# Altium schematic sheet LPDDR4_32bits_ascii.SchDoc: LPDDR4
size A3; Date: Not used; ApprovedBy: Not used; CheckedBy: Not used; Author: Not used; CompanyName: STMicroelectronics; DrawnBy: Not used; Engineer: Not used; Organization: Not used; Address1: Not used; Address2: Not used; Address3: Not used; Address4: Not used; DocumentNumber: 6; Revision: Not used; SheetNumber: 6; SheetTotal: 7
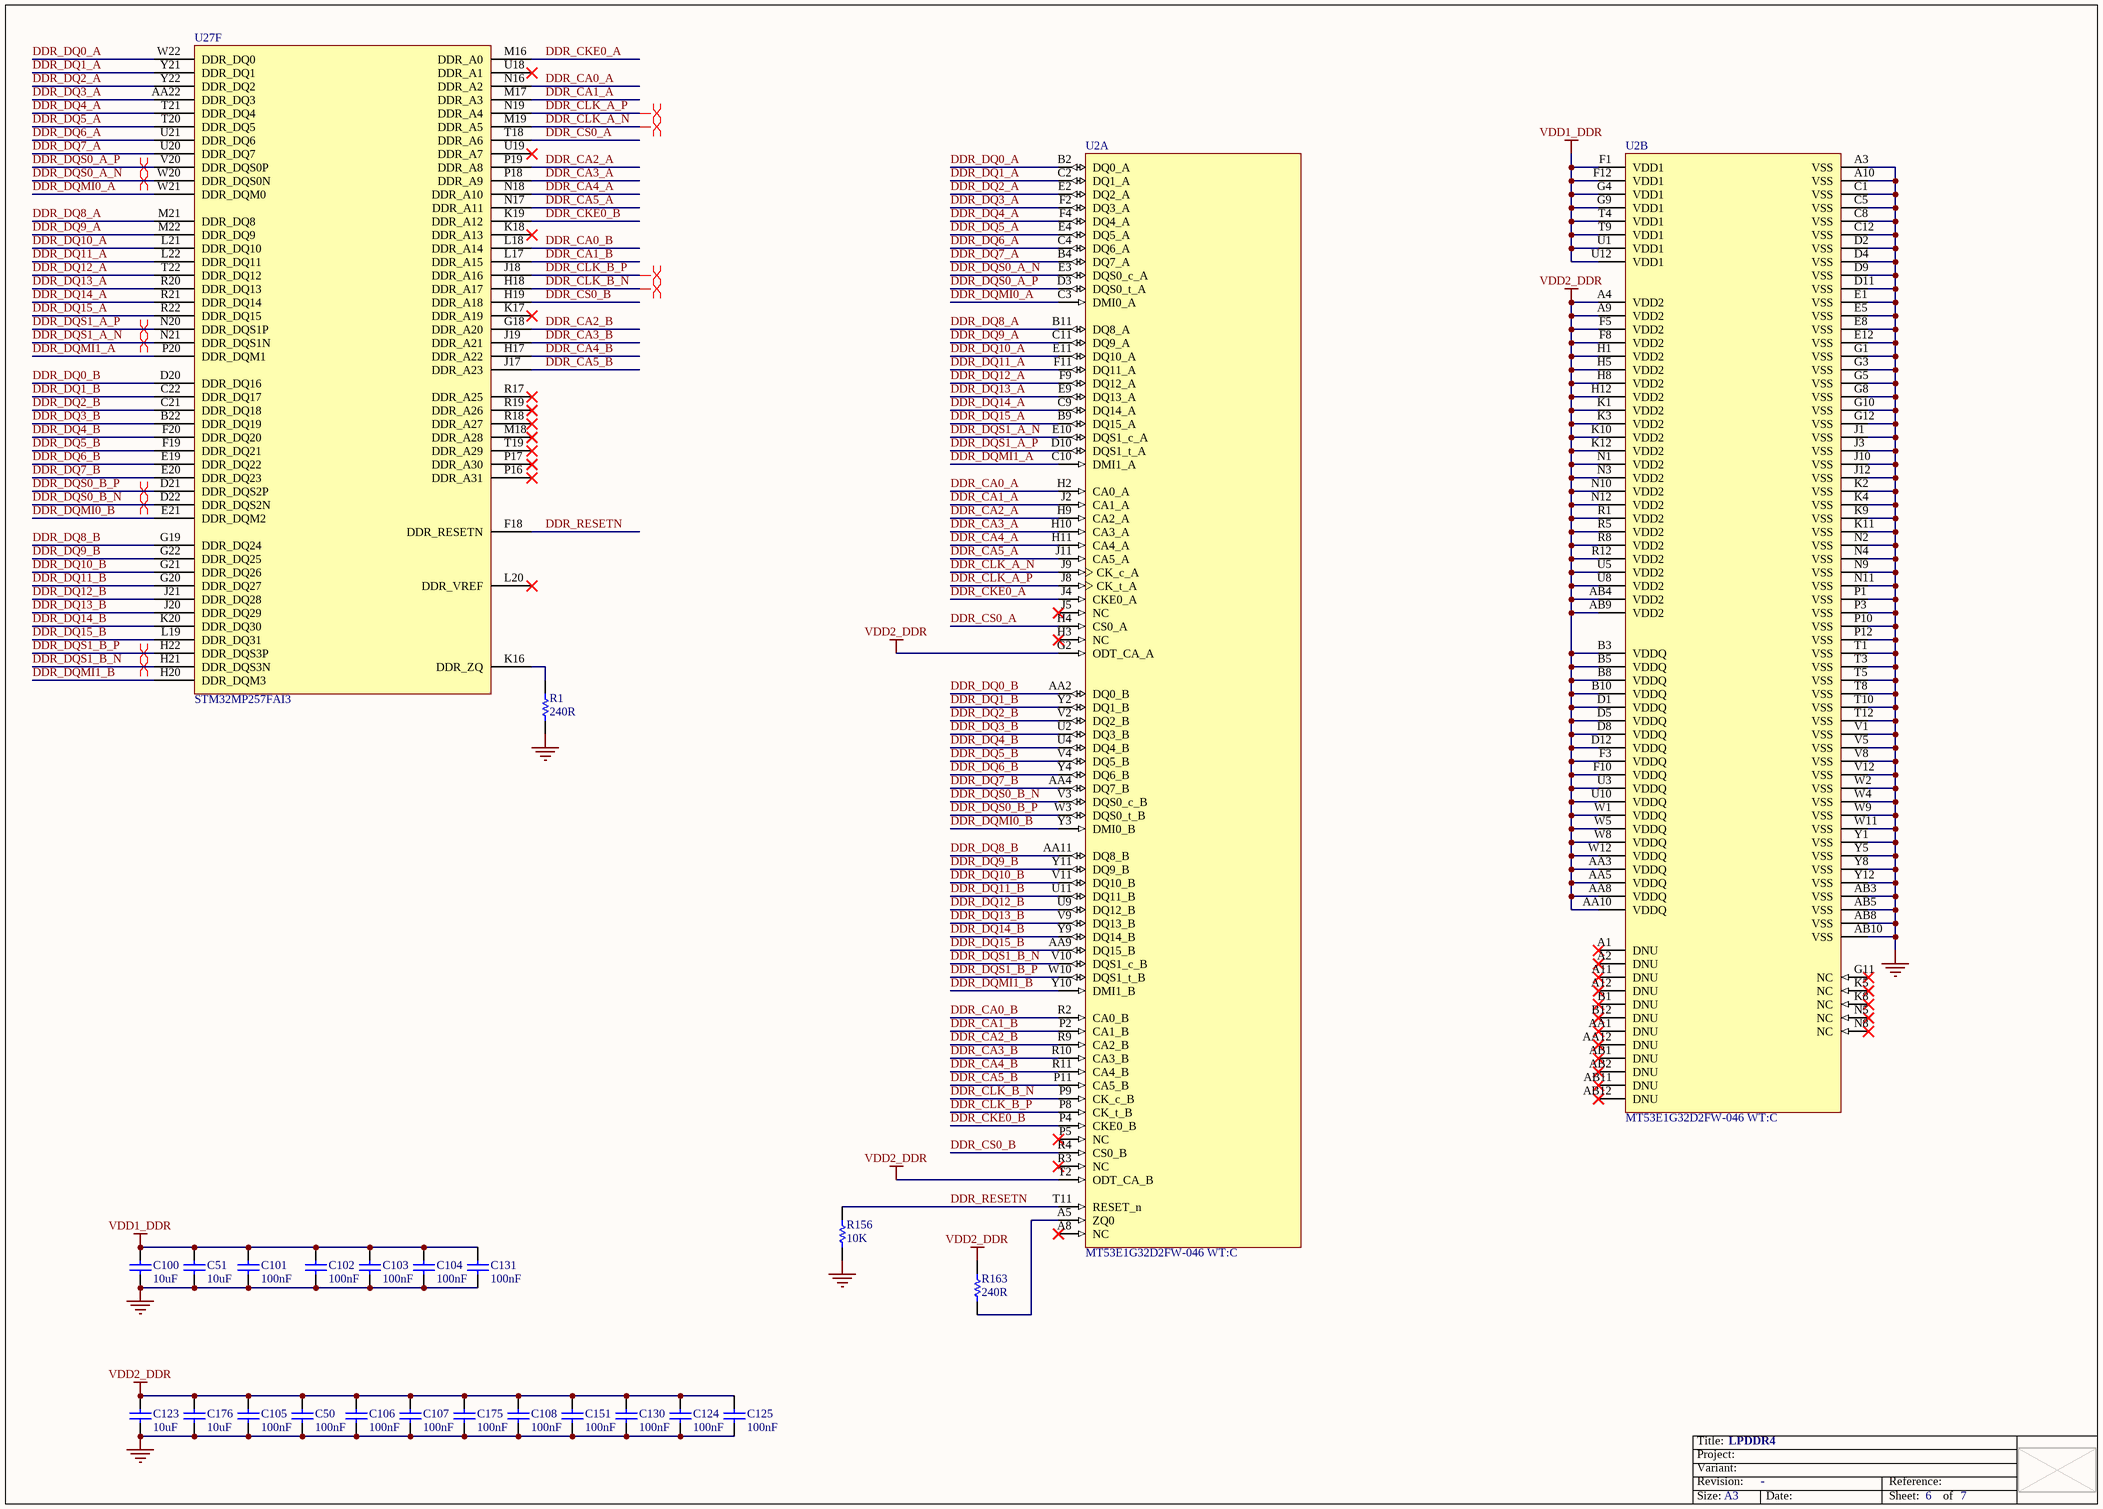
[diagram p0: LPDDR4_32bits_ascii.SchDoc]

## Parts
C50  value 100nF  [C0402]  (hidden comment: Capacitor)
C51  value 10uF  [C0603]  (hidden comment: Capacitor)
C100  value 10uF  [C0603]  (hidden comment: Capacitor)
C101  value 100nF  [C0402]  (hidden comment: Capacitor)
C102  value 100nF  [C0402]  (hidden comment: Capacitor)
C103  value 100nF  [C0402]  (hidden comment: Capacitor)
C104  value 100nF  [C0402]  (hidden comment: Capacitor)
C105  value 100nF  [C0402]  (hidden comment: Capacitor)
C106  value 100nF  [C0402]  (hidden comment: Capacitor)
C107  value 100nF  [C0402]  (hidden comment: Capacitor)
C108  value 100nF  [C0402]  (hidden comment: Capacitor)
C123  value 10uF  [C0603]  (hidden comment: Capacitor)
C124  value 100nF  [C0402]  (hidden comment: Capacitor)
C125  value 100nF  [C0402]  (hidden comment: Capacitor)
C130  value 100nF  [C0402]  (hidden comment: Capacitor)
C131  value 100nF  [C0402]  (hidden comment: Capacitor)
C151  value 100nF  [C0402]  (hidden comment: Capacitor)
C175  value 100nF  [C0402]  (hidden comment: Capacitor)
C176  value 10uF  [C0603]  (hidden comment: Capacitor)
R1  value 240R  [R0201_H0P23]  (hidden comment: Resistor)
R156  value 10K  [R0402]  (hidden comment: Resistor)
R163  value 240R  [R0201_H0P23]  (hidden comment: Resistor)
U2  MT53E1G32D2FW-046 WT:C  [ICC_TFBGA200_10X14P5_P080_H1P05_PS0P3]  (parts A,B of 2)
U27  STM32MP257FAI3  [ICC_LFBGA436_18X18_P080_H1P70_STM32MP257_CODE-B0D1]  (part F of 9)

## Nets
GND: C50.2 C51.1 C100.1 C101.1 C102.1 C103.1 C104.1 C105.1 C106.2 C107.2 C108.2 C123.1 C124.2 C125.2 C130.2 C131.1 C151.2 C175.2 C176.1 R1.1 R156.1 U2.A3(VSS) U2.A10(VSS) U2.AB3(VSS) U2.AB5(VSS) U2.AB8(VSS) U2.AB10(VSS) U2.C1(VSS) U2.C5(VSS) U2.C8(VSS) U2.C12(VSS) U2.D2(VSS) U2.D4(VSS) U2.D9(VSS) U2.D11(VSS) U2.E1(VSS) U2.E5(VSS) U2.E8(VSS) U2.E12(VSS) U2.G1(VSS) U2.G3(VSS) U2.G5(VSS) U2.G8(VSS) U2.G10(VSS) U2.G12(VSS) U2.J1(VSS) U2.J3(VSS) U2.J10(VSS) U2.J12(VSS) U2.K2(VSS) U2.K4(VSS) U2.K9(VSS) U2.K11(VSS) U2.N2(VSS) U2.N4(VSS) U2.N9(VSS) U2.N11(VSS) U2.P1(VSS) U2.P3(VSS) U2.P10(VSS) U2.P12(VSS) U2.T1(VSS) U2.T3(VSS) U2.T5(VSS) U2.T8(VSS) U2.T10(VSS) U2.T12(VSS) U2.V1(VSS) U2.V5(VSS) U2.V8(VSS) U2.V12(VSS) U2.W2(VSS) U2.W4(VSS) U2.W9(VSS) U2.W11(VSS) U2.Y1(VSS) U2.Y5(VSS) U2.Y8(VSS) U2.Y12(VSS)
VDD1_DDR: C51.2 C100.2 C101.2 C102.2 C103.2 C104.2 C131.2 U2.F1(VDD1) U2.F12(VDD1) U2.G4(VDD1) U2.G9(VDD1) U2.T4(VDD1) U2.T9(VDD1) U2.U1(VDD1) U2.U12(VDD1)
VDD2_DDR: C50.1 C105.2 C106.1 C107.1 C108.1 C123.2 C124.1 C125.1 C130.1 C151.1 C175.1 C176.2 R163.2 U2.A4(VDD2) U2.A9(VDD2) U2.AA3(VDDQ) U2.AA5(VDDQ) U2.AA8(VDDQ) U2.AA10(VDDQ) U2.AB4(VDD2) U2.AB9(VDD2) U2.B3(VDDQ) U2.B5(VDDQ) U2.B8(VDDQ) U2.B10(VDDQ) U2.D1(VDDQ) U2.D5(VDDQ) U2.D8(VDDQ) U2.D12(VDDQ) U2.F3(VDDQ) U2.F5(VDD2) U2.F8(VDD2) U2.F10(VDDQ) U2.G2(ODT_CA_A) U2.H1(VDD2) U2.H5(VDD2) U2.H8(VDD2) U2.H12(VDD2) U2.K1(VDD2) U2.K3(VDD2) U2.K10(VDD2) U2.K12(VDD2) U2.N1(VDD2) U2.N3(VDD2) U2.N10(VDD2) U2.N12(VDD2) U2.R1(VDD2) U2.R5(VDD2) U2.R8(VDD2) U2.R12(VDD2) U2.T2(ODT_CA_B) U2.U3(VDDQ) U2.U5(VDD2) U2.U8(VDD2) U2.U10(VDDQ) U2.W1(VDDQ) U2.W5(VDDQ) U2.W8(VDDQ) U2.W12(VDDQ)
DDR_CA0_A: U2.H2(CA0_A) U27.N16(DDR_A2)
DDR_CA0_B: U2.R2(CA0_B) U27.L18(DDR_A14)
DDR_CA1_A: U2.J2(CA1_A) U27.M17(DDR_A3)
DDR_CA1_B: U2.P2(CA1_B) U27.L17(DDR_A15)
DDR_CA2_A: U2.H9(CA2_A) U27.P19(DDR_A8)
DDR_CA2_B: U2.R9(CA2_B) U27.G18(DDR_A20)
DDR_CA3_A: U2.H10(CA3_A) U27.P18(DDR_A9)
DDR_CA3_B: U2.R10(CA3_B) U27.J19(DDR_A21)
DDR_CA4_A: U2.H11(CA4_A) U27.N18(DDR_A10)
DDR_CA4_B: U2.R11(CA4_B) U27.H17(DDR_A22)
DDR_CA5_A: U2.J11(CA5_A) U27.N17(DDR_A11)
DDR_CA5_B: U2.P11(CA5_B) U27.J17(DDR_A23)
DDR_CKE0_A: U2.J4(CKE0_A) U27.M16(DDR_A0)
DDR_CKE0_B: U2.P4(CKE0_B) U27.K19(DDR_A12)
DDR_CLK_A_N: U2.J9(CK_c_A) U27.M19(DDR_A5)
DDR_CLK_A_P: U2.J8(CK_t_A) U27.N19(DDR_A4)
DDR_CLK_B_N: U2.P9(CK_c_B) U27.H18(DDR_A17)
DDR_CLK_B_P: U2.P8(CK_t_B) U27.J18(DDR_A16)
DDR_CS0_A: U2.H4(CS0_A) U27.T18(DDR_A6)
DDR_CS0_B: U2.R4(CS0_B) U27.H19(DDR_A18)
DDR_DQ0_A: U2.B2(DQ0_A) U27.W22(DDR_DQ0)
DDR_DQ0_B: U2.AA2(DQ0_B) U27.D20(DDR_DQ16)
DDR_DQ1_A: U2.C2(DQ1_A) U27.Y21(DDR_DQ1)
DDR_DQ1_B: U2.Y2(DQ1_B) U27.C22(DDR_DQ17)
DDR_DQ2_A: U2.E2(DQ2_A) U27.Y22(DDR_DQ2)
DDR_DQ2_B: U2.V2(DQ2_B) U27.C21(DDR_DQ18)
DDR_DQ3_A: U2.F2(DQ3_A) U27.AA22(DDR_DQ3)
DDR_DQ3_B: U2.U2(DQ3_B) U27.B22(DDR_DQ19)
DDR_DQ4_A: U2.F4(DQ4_A) U27.T21(DDR_DQ4)
DDR_DQ4_B: U2.U4(DQ4_B) U27.F20(DDR_DQ20)
DDR_DQ5_A: U2.E4(DQ5_A) U27.T20(DDR_DQ5)
DDR_DQ5_B: U2.V4(DQ5_B) U27.F19(DDR_DQ21)
DDR_DQ6_A: U2.C4(DQ6_A) U27.U21(DDR_DQ6)
DDR_DQ6_B: U2.Y4(DQ6_B) U27.E19(DDR_DQ22)
DDR_DQ7_A: U2.B4(DQ7_A) U27.U20(DDR_DQ7)
DDR_DQ7_B: U2.AA4(DQ7_B) U27.E20(DDR_DQ23)
DDR_DQ8_A: U2.B11(DQ8_A) U27.M21(DDR_DQ8)
DDR_DQ8_B: U2.AA11(DQ8_B) U27.G19(DDR_DQ24)
DDR_DQ9_A: U2.C11(DQ9_A) U27.M22(DDR_DQ9)
DDR_DQ9_B: U2.Y11(DQ9_B) U27.G22(DDR_DQ25)
DDR_DQ10_A: U2.E11(DQ10_A) U27.L21(DDR_DQ10)
DDR_DQ10_B: U2.V11(DQ10_B) U27.G21(DDR_DQ26)
DDR_DQ11_A: U2.F11(DQ11_A) U27.L22(DDR_DQ11)
DDR_DQ11_B: U2.U11(DQ11_B) U27.G20(DDR_DQ27)
DDR_DQ12_A: U2.F9(DQ12_A) U27.T22(DDR_DQ12)
DDR_DQ12_B: U2.U9(DQ12_B) U27.J21(DDR_DQ28)
DDR_DQ13_A: U2.E9(DQ13_A) U27.R20(DDR_DQ13)
DDR_DQ13_B: U2.V9(DQ13_B) U27.J20(DDR_DQ29)
DDR_DQ14_A: U2.C9(DQ14_A) U27.R21(DDR_DQ14)
DDR_DQ14_B: U2.Y9(DQ14_B) U27.K20(DDR_DQ30)
DDR_DQ15_A: U2.B9(DQ15_A) U27.R22(DDR_DQ15)
DDR_DQ15_B: U2.AA9(DQ15_B) U27.L19(DDR_DQ31)
DDR_DQMI0_A: U2.C3(DMI0_A) U27.W21(DDR_DQM0)
DDR_DQMI0_B: U2.Y3(DMI0_B) U27.E21(DDR_DQM2)
DDR_DQMI1_A: U2.C10(DMI1_A) U27.P20(DDR_DQM1)
DDR_DQMI1_B: U2.Y10(DMI1_B) U27.H20(DDR_DQM3)
DDR_DQS0_A_N: U2.E3(DQS0_c_A) U27.W20(DDR_DQS0N)
DDR_DQS0_A_P: U2.D3(DQS0_t_A) U27.V20(DDR_DQS0P)
DDR_DQS0_B_N: U2.V3(DQS0_c_B) U27.D22(DDR_DQS2N)
DDR_DQS0_B_P: U2.W3(DQS0_t_B) U27.D21(DDR_DQS2P)
DDR_DQS1_A_N: U2.E10(DQS1_c_A) U27.N21(DDR_DQS1N)
DDR_DQS1_A_P: U2.D10(DQS1_t_A) U27.N20(DDR_DQS1P)
DDR_DQS1_B_N: U2.V10(DQS1_c_B) U27.H21(DDR_DQS3N)
DDR_DQS1_B_P: U2.W10(DQS1_t_B) U27.H22(DDR_DQS3P)
DDR_RESETN: R156.2 U2.T11(RESET_n) U27.F18(DDR_RESETN)
NetR1_2: R1.2 U27.K16(DDR_ZQ)
NetR163_1: R163.1 U2.A5(ZQ0)

Not connected (* = marked no-connect by the designer): U2 A1(DNU)* A2(DNU)* A8(NC)* A11(DNU)* A12(DNU)* AA1(DNU)* AA12(DNU)* AB1(DNU)* AB2(DNU)* AB11(DNU)* AB12(DNU)* B1(DNU)* B12(DNU)* G11(NC)* H3(NC)* J5(NC)* K5(NC)* K8(NC)* N5(NC)* N8(NC)* P5(NC)* R3(NC)*; U27 K17(DDR_A19)* K18(DDR_A13)* L20(DDR_VREF)* M18(DDR_A28)* P16(DDR_A31)* P17(DDR_A30)* R17(DDR_A25)* R18(DDR_A27)* R19(DDR_A26)* T19(DDR_A29)* U18(DDR_A1)* U19(DDR_A7)*

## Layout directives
differential pair: DDR_CLK_A_N, DDR_CLK_A_P, DDR_CLK_B_N, DDR_CLK_B_P, DDR_DQS0_A_N, DDR_DQS0_A_P, DDR_DQS0_B_N, DDR_DQS0_B_P, DDR_DQS1_A_N, DDR_DQS1_A_P, DDR_DQS1_B_N, DDR_DQS1_B_P

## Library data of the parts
C50 C101-C108 C124 C125 C130 C131 C151 C175 = MCD-00006: Capacitor, MLCC, 100nF, 16V, X7R, +/-10%, 0402, T=0.5mm; Part_Preference: Recommended; Manufacturer: YAGEO; Manufacturer_Part_Number: CC0402KRX7R7BB104; Alternate_Manufacturer: MURATA; Alternate_Manufacturer_Part_Number: GCM155R71C104KA55D; Order_Code_RS: 616-9701
C51 C100 C123 C176 = MCD-01341: Capacitor, MLCC, 10uF, 6V3, X5R, +/-20%, 0603, T=0,8mm; Part_Preference: Recommended; Manufacturer: MURATA; Manufacturer_Part_Number: GRM188R60J106ME47D; Alternate_Manufacturer_Part_Number: GRM188R60J106ME84D
R1 R163 = MCD-02253: Resistor, 240R, 0201, +/-1%, 1/20W; Part_Preference: Recommended; Manufacturer: YAGEO; Manufacturer_Part_Number: RC0201FR-07240RL; Component_Country_Of_Origin: China; ID: 4353; ShowFields: YES
R156 = MCD-00053: Resistor, 10K, 0402, +/-1%, 1/16W; BMS_Part_Number: 9131590; Part_Preference: Recommended; Manufacturer: YAGEO; Manufacturer_Part_Number: RC0402FR-0710KL; Component_Country_Of_Origin: China; ID: 2539; ShowFields: YES
U2 = MCD-04160: Memory, LPDDR4 SDRAM,1V8, 32Gbit, 2133MHz; Part_Type: IC; Part_Preference: Recommended; Manufacturer: MICRON; ShowFields: YES; ID: 6276
U27 = MCD-02000: MPU, ARM Cortex-A35 + M33 32-bit MPU, 808KB RAM, With Crypto; Part_Type: IC; Part_Preference: Recommended; Manufacturer: STMICROELECTRONICS; Manufacturer_HQ_COO: EU; Component_Country_Of_Origin: Unknown; ShowFields: YES; ID: 4100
